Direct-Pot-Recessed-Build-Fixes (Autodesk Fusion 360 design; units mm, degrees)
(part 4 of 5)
work_plane "WorkPlane16" AlongDistance 17 ExtraOffset 0
sketch "Reinforced roof over support-free pivot bore (1)" plane through (17, 0, 0) normal (1, 0, 0) x axis (0, 0, -1)
  line L1 (-17.9, -29) -> (-17.9, -41)
  line L2 (-20, -29) -> (-17.9, -29)
  line L3 (-20, -41) -> (-20, -29)
  line L4 (-17.9, -41) -> (-20, -41)
extrude "Extrude16" add sketch "Reinforced roof over support-free pivot bore (1)" along normal blind 3
work_plane "WorkPlane17" AlongDistance 17 ExtraOffset 0
sketch "Flat print foot below roller cheek (1)" plane through (17, 0, 0) normal (1, 0, 0) x axis (0, 0, -1)
  line L1 (-6, 6) -> (-6, -6)
  line L2 (-12, 6) -> (-6, 6)
  line L3 (-12, -6) -> (-12, 6)
  line L4 (-6, -6) -> (-12, -6)
extrude "Extrude17" add sketch "Flat print foot below roller cheek (1)" along normal blind 3
work_plane "WorkPlane18" AlongDistance 3.9 ExtraOffset 0
sketch "Follower horizontal bore 45 degree roof" plane through (3.9, 0, 0) normal (1, 0, 0) x axis (0, 0, -1)
  line L1 (-14.9345, -32.0655) -> (-14.9345, -37.9345)
  line L2 (-17.869, -35) -> (-14.9345, -32.0655)
  line L3 (-14.9345, -37.9345) -> (-17.869, -35)
extrude "Extrude18" cut sketch "Follower horizontal bore 45 degree roof" along normal blind 16.2
work_plane "WorkPlane19" AlongDistance 3.9 ExtraOffset 0
sketch "Follower horizontal bore 45 degree roof (1)" plane through (3.9, 0, 0) normal (1, 0, 0) x axis (0, 0, -1)
  line L1 (-13.2021, 1.2021) -> (-13.2021, -1.2021)
  line L2 (-14.4042, 0) -> (-13.2021, 1.2021)
  line L3 (-13.2021, -1.2021) -> (-14.4042, 0)
extrude "Extrude19" cut sketch "Follower horizontal bore 45 degree roof (1)" along normal blind 16.2
work_plane "WorkPlane8" AlongDistance 49.65 ExtraOffset 0
sketch "Continuous support beneath lower output prong" plane through (49.65, 0, 0) normal (1, 0, 0) x axis (0, 0, -1)
  line L1 (-57, 2) -> (-57, -2)
  line L2 (-61, 2) -> (-57, 2)
  line L3 (-61, -2) -> (-61, 2)
  line L4 (-57, -2) -> (-61, -2)
extrude "Extrude8" add sketch "Continuous support beneath lower output prong" along normal blind 9
work_plane "WorkPlane11" AlongDistance 9 ExtraOffset 0
sketch "Upright grip head pocket roof" plane through (9, 0, 0) normal (1, 0, 0) x axis (0, 0, -1)
  line L1 (-182.192, -2.192) -> (-182.192, 2.192)
  line L2 (-184.3841, 0) -> (-182.192, -2.192)
  line L3 (-182.192, 2.192) -> (-184.3841, 0)
extrude "Extrude10" cut sketch "Upright grip head pocket roof" along normal blind 16
work_plane "WorkPlane12" AlongDistance 9 ExtraOffset 0
sketch "Upright grip head pocket roof (1)" plane through (9, 0, 0) normal (1, 0, 0) x axis (0, 0, -1)
  line L1 (-192.192, -2.192) -> (-192.192, 2.192)
  line L2 (-194.3841, 0) -> (-192.192, -2.192)
  line L3 (-192.192, 2.192) -> (-194.3841, 0)
extrude "Extrude11" cut sketch "Upright grip head pocket roof (1)" along normal blind 16
work_plane "WorkPlane11" AlongDistance -6.8 ExtraOffset 0
sketch "Shaft half joining insert pocket" plane through (0, -6.8, 0) normal (0, 1, 0) x axis (1, 0, 0)
  circle C1 centre (-15, -65) radius 1.7
extrude "Extrude11" cut sketch "Shaft half joining insert pocket" along normal blind 6.9
work_plane "WorkPlane12" AlongDistance -0.1 ExtraOffset 0
sketch "Shaft half joining screw clearance" plane through (0, -0.1, 0) normal (0, 1, 0) x axis (1, 0, 0)
  circle C1 centre (-15, -65) radius 1.7
extrude "Extrude12" cut sketch "Shaft half joining screw clearance" along normal blind 6.7
work_plane "WorkPlane13" AlongDistance 3.5 ExtraOffset 0
sketch "Flush shaft joining cap head" plane through (0, 3.5, 0) normal (0, 1, 0) x axis (1, 0, 0)
  circle C1 centre (-15, -65) radius 3.1
extrude "Extrude13" cut sketch "Flush shaft joining cap head" along normal blind 3.1
work_plane "WorkPlane1" AlongDistance -4.5 ExtraOffset 0
sketch "Shaft joining M3x8 -15" plane through (0, -4.5, 0) normal (0, 1, 0) x axis (1, 0, 0)
  circle C1 centre (-15, -65) radius 1.5
extrude "Extrude1" new body sketch "Shaft joining M3x8 -15" along normal blind 8 bodies "HARDWARE Shaft joining M3x8 -15"
work_plane "WorkPlane2" AlongDistance 3.5 ExtraOffset 0
sketch "Button head" plane through (0, 3.5, 0) normal (0, 1, 0) x axis (1, 0, 0)
  circle C1 centre (-15, -65) radius 2.75
extrude "Extrude2" add sketch "Button head" along normal blind 3
work_plane "WorkPlane14" AlongDistance -6.8 ExtraOffset 0
sketch "Shaft half joining insert pocket (1)" plane through (0, -6.8, 0) normal (0, 1, 0) x axis (1, 0, 0)
  circle C1 centre (15, -65) radius 1.7
extrude "Extrude14" cut sketch "Shaft half joining insert pocket (1)" along normal blind 6.9
work_plane "WorkPlane15" AlongDistance -0.1 ExtraOffset 0
sketch "Shaft half joining screw clearance (1)" plane through (0, -0.1, 0) normal (0, 1, 0) x axis (1, 0, 0)
  circle C1 centre (15, -65) radius 1.7
extrude "Extrude15" cut sketch "Shaft half joining screw clearance (1)" along normal blind 6.7
work_plane "WorkPlane16" AlongDistance 3.5 ExtraOffset 0
sketch "Flush shaft joining cap head (1)" plane through (0, 3.5, 0) normal (0, 1, 0) x axis (1, 0, 0)
  circle C1 centre (15, -65) radius 3.1
extrude "Extrude16" cut sketch "Flush shaft joining cap head (1)" along normal blind 3.1
work_plane "WorkPlane1" AlongDistance -4.5 ExtraOffset 0
sketch "Shaft joining M3x8 15" plane through (0, -4.5, 0) normal (0, 1, 0) x axis (1, 0, 0)
  circle C1 centre (15, -65) radius 1.5
extrude "Extrude1" new body sketch "Shaft joining M3x8 15" along normal blind 8 bodies "HARDWARE Shaft joining M3x8 15"
work_plane "WorkPlane2" AlongDistance 3.5 ExtraOffset 0
sketch "Button head" plane through (0, 3.5, 0) normal (0, 1, 0) x axis (1, 0, 0)
  circle C1 centre (15, -65) radius 2.75
extrude "Extrude2" add sketch "Button head" along normal blind 3
work_plane "WorkPlane17" AlongDistance -6.6 ExtraOffset 0
sketch "Loose alignment key pocket" plane through (-6.6, 0, 0) normal (1, 0, 0) x axis (0, 0, -1)
  line L1 (-61, 1.6) -> (-61, -1.6)
  line L2 (-69, 1.6) -> (-61, 1.6)
  line L3 (-69, -1.6) -> (-69, 1.6)
  line L4 (-61, -1.6) -> (-69, -1.6)
extrude "Extrude17" cut sketch "Loose alignment key pocket" along normal blind 3.2
work_plane "WorkPlane1" AlongDistance -6.5 ExtraOffset 0
sketch "Loose flat printable alignment key" plane through (-6.5, 0, 0) normal (1, 0, 0) x axis (0, 0, -1)
  line L1 (-61.1, 1.5) -> (-61.1, -1.5)
  line L2 (-68.9, 1.5) -> (-61.1, 1.5)
  line L3 (-68.9, -1.5) -> (-68.9, 1.5)
  line L4 (-61.1, -1.5) -> (-68.9, -1.5)
extrude "Extrude1" new body sketch "Loose flat printable alignment key" along normal blind 3 bodies "P28 Shaft alignment key -5"
work_plane "WorkPlane18" AlongDistance 3.4 ExtraOffset 0
sketch "Loose alignment key pocket (1)" plane through (3.4, 0, 0) normal (1, 0, 0) x axis (0, 0, -1)
  line L1 (-61, 1.6) -> (-61, -1.6)
  line L2 (-69, 1.6) -> (-61, 1.6)
  line L3 (-69, -1.6) -> (-69, 1.6)
  line L4 (-61, -1.6) -> (-69, -1.6)
extrude "Extrude18" cut sketch "Loose alignment key pocket (1)" along normal blind 3.2
work_plane "WorkPlane1" AlongDistance 3.5 ExtraOffset 0
sketch "Loose flat printable alignment key" plane through (3.5, 0, 0) normal (1, 0, 0) x axis (0, 0, -1)
  line L1 (-61.1, 1.5) -> (-61.1, -1.5)
  line L2 (-68.9, 1.5) -> (-61.1, 1.5)
  line L3 (-68.9, -1.5) -> (-68.9, 1.5)
  line L4 (-61.1, -1.5) -> (-68.9, -1.5)
extrude "Extrude1" new body sketch "Loose flat printable alignment key" along normal blind 3 bodies "P28 Shaft alignment key 5"
split "Split1" bodies "P05 Shaft upper half"
work_plane "WorkPlane19" AlongDistance -5 ExtraOffset 0
sketch "Direct cap-head rotor clamp seat" plane through (-5, 0, 0) normal (1, 0, 0) x axis (0, 0, -1)
  line L1 (-60, 22.5) -> (-60, 22)
  line L2 (-70, 22.5) -> (-60, 22.5)
  line L3 (-70, 22) -> (-70, 22.5)
  line L4 (-60, 22) -> (-70, 22)
extrude "Extrude19" add sketch "Direct cap-head rotor clamp seat" along normal blind 10
work_plane "WorkPlane20" AlongDistance 21.9 ExtraOffset 0
sketch "Restore rotor screw through raised seat" plane through (0, 21.9, 0) normal (0, 1, 0) x axis (1, 0, 0)
  circle C1 centre (0, -65) radius 1.7
extrude "Extrude20" cut sketch "Restore rotor screw through raised seat" along normal blind 0.7
work_plane "WorkPlane1" AlongDistance -39.35 ExtraOffset 0
sketch "Main shaft cap M3x8 cap head" plane through (-39.35, 0, 0) normal (1, 0, 0) x axis (0, 0, -1)
  circle C1 centre (-65, 0) radius 1.5
extrude "Extrude1" new body sketch "Main shaft cap M3x8 cap head" along normal blind 8 bodies "HARDWARE Main shaft cap M3x8 cap head"
work_plane "WorkPlane2" AlongDistance -42.35 ExtraOffset 0
sketch "Button head" plane through (-42.35, 0, 0) normal (1, 0, 0) x axis (0, 0, -1)
  circle C1 centre (-65, 0) radius 2.75
extrude "Extrude2" add sketch "Button head" along normal blind 3
work_plane "WorkPlane1" AlongDistance 2 ExtraOffset 0
sketch "Cam M3x10 cap head -45" plane through (2, 0, 0) normal (1, 0, 0) x axis (0, 0, -1)
  circle C1 centre (-39.5442, 25.4558) radius 1.5
extrude "Extrude1" new body sketch "Cam M3x10 cap head -45" along normal blind 10 bodies "HARDWARE Cam M3x10 cap head -45"
work_plane "WorkPlane2" AlongDistance 12 ExtraOffset 0
sketch "Button head" plane through (12, 0, 0) normal (1, 0, 0) x axis (0, 0, -1)
  circle C1 centre (-39.5442, 25.4558) radius 2.75
extrude "Extrude2" add sketch "Button head" along normal blind 3
work_plane "WorkPlane1" AlongDistance 2 ExtraOffset 0
sketch "Cam M3x10 cap head 0" plane through (2, 0, 0) normal (1, 0, 0) x axis (0, 0, -1)
  circle C1 centre (-29, 0) radius 1.5
extrude "Extrude1" new body sketch "Cam M3x10 cap head 0" along normal blind 10 bodies "HARDWARE Cam M3x10 cap head 0"
work_plane "WorkPlane2" AlongDistance 12 ExtraOffset 0
sketch "Button head" plane through (12, 0, 0) normal (1, 0, 0) x axis (0, 0, -1)
  circle C1 centre (-29, 0) radius 2.75
extrude "Extrude2" add sketch "Button head" along normal blind 3
work_plane "WorkPlane1" AlongDistance 2 ExtraOffset 0
sketch "Cam M3x10 cap head 45" plane through (2, 0, 0) normal (1, 0, 0) x axis (0, 0, -1)
  circle C1 centre (-39.5442, -25.4558) radius 1.5
extrude "Extrude1" new body sketch "Cam M3x10 cap head 45" along normal blind 10 bodies "HARDWARE Cam M3x10 cap head 45"
work_plane "WorkPlane2" AlongDistance 12 ExtraOffset 0
sketch "Button head" plane through (12, 0, 0) normal (1, 0, 0) x axis (0, 0, -1)
  circle C1 centre (-39.5442, -25.4558) radius 2.75
extrude "Extrude2" add sketch "Button head" along normal blind 3
work_plane "WorkPlane1" AlongDistance 0 ExtraOffset 0
sketch "Roller axle M3x20 cap head" plane through (0, 0, 0) normal (1, 0, 0) x axis (0, 0, -1)
  circle C1 centre (-12, 0) radius 1.5
extrude "Extrude1" new body sketch "Roller axle M3x20 cap head" along normal blind 20 bodies "HARDWARE Roller axle M3x20 cap head"
work_plane "WorkPlane2" AlongDistance 20 ExtraOffset 0
sketch "Button head" plane through (20, 0, 0) normal (1, 0, 0) x axis (0, 0, -1)
  circle C1 centre (-12, 0) radius 2.75
extrude "Extrude2" add sketch "Button head" along normal blind 3
work_plane "WorkPlane1" AlongDistance -36 ExtraOffset 0
sketch "Crossblock M3x20 cap head (-62, -1)" plane through (-36, 0, 0) normal (1, 0, 0) x axis (0, 0, -1)
  circle C1 centre (-53.5, -62) radius 1.5
extrude "Extrude1" new body sketch "Crossblock M3x20 cap head (-62, -1)" along normal blind 20 bodies "HARDWARE Crossblock M3x20 cap head (-62, -1)"
work_plane "WorkPlane2" AlongDistance -39 ExtraOffset 0
sketch "Button head" plane through (-39, 0, 0) normal (1, 0, 0) x axis (0, 0, -1)
  circle C1 centre (-53.5, -62) radius 2.75
extrude "Extrude2" add sketch "Button head" along normal blind 3
work_plane "WorkPlane1" AlongDistance 16 ExtraOffset 0
sketch "Crossblock M3x20 cap head (-62, 1)" plane through (16, 0, 0) normal (1, 0, 0) x axis (0, 0, -1)
  circle C1 centre (-53.5, -62) radius 1.5
extrude "Extrude1" new body sketch "Crossblock M3x20 cap head (-62, 1)" along normal blind 20 bodies "HARDWARE Crossblock M3x20 cap head (-62, 1)"
work_plane "WorkPlane2" AlongDistance 36 ExtraOffset 0
sketch "Button head" plane through (36, 0, 0) normal (1, 0, 0) x axis (0, 0, -1)
  circle C1 centre (-53.5, -62) radius 2.75
extrude "Extrude2" add sketch "Button head" along normal blind 3
work_plane "WorkPlane1" AlongDistance -36 ExtraOffset 0
sketch "Crossblock M3x20 cap head (-70, -1)" plane through (-36, 0, 0) normal (1, 0, 0) x axis (0, 0, -1)
  circle C1 centre (-53.5, -70) radius 1.5
extrude "Extrude1" new body sketch "Crossblock M3x20 cap head (-70, -1)" along normal blind 20 bodies "HARDWARE Crossblock M3x20 cap head (-70, -1)"
work_plane "WorkPlane2" AlongDistance -39 ExtraOffset 0
sketch "Button head" plane through (-39, 0, 0) normal (1, 0, 0) x axis (0, 0, -1)
  circle C1 centre (-53.5, -70) radius 2.75
extrude "Extrude2" add sketch "Button head" along normal blind 3
work_plane "WorkPlane1" AlongDistance 16 ExtraOffset 0
sketch "Crossblock M3x20 cap head (-70, 1)" plane through (16, 0, 0) normal (1, 0, 0) x axis (0, 0, -1)
  circle C1 centre (-53.5, -70) radius 1.5
extrude "Extrude1" new body sketch "Crossblock M3x20 cap head (-70, 1)" along normal blind 20 bodies "HARDWARE Crossblock M3x20 cap head (-70, 1)"
work_plane "WorkPlane2" AlongDistance 36 ExtraOffset 0
sketch "Button head" plane through (36, 0, 0) normal (1, 0, 0) x axis (0, 0, -1)
  circle C1 centre (-53.5, -70) radius 2.75
extrude "Extrude2" add sketch "Button head" along normal blind 3
work_plane "WorkPlane1" AlongDistance 6.5 ExtraOffset 0
sketch "Rotor clamp M3x16 cap head" plane through (0, 6.5, 0) normal (0, 1, 0) x axis (1, 0, 0)
  circle C1 centre (0, -65) radius 1.5
extrude "Extrude1" new body sketch "Rotor clamp M3x16 cap head" along normal blind 16 bodies "HARDWARE Rotor clamp M3x16 cap head"
work_plane "WorkPlane2" AlongDistance 22.5 ExtraOffset 0
sketch "Button head" plane through (0, 22.5, 0) normal (0, 1, 0) x axis (1, 0, 0)
  circle C1 centre (0, -65) radius 2.75
extrude "Extrude2" add sketch "Button head" along normal blind 3
work_plane "WorkPlane20" AlongDistance 3.9 ExtraOffset 0
sketch "Restore axle bore after adding print feet" plane through (3.9, 0, 0) normal (1, 0, 0) x axis (0, 0, -1)
  circle C1 centre (-12, 0) radius 1.7
extrude "Extrude20" cut sketch "Restore axle bore after adding print feet" along normal blind 16.2
work_plane "WorkPlane21" AlongDistance 3.9 ExtraOffset 0
sketch "Restore nut installation recess after print foot" plane through (3.9, 0, 0) normal (1, 0, 0) x axis (0, 0, -1)
  line L1 (-14.9, 1.6743) -> (-12, 3.3486)
  line L2 (-14.9, -1.6743) -> (-14.9, 1.6743)
  line L3 (-12, -3.3486) -> (-14.9, -1.6743)
  line L4 (-9.1, -1.6743) -> (-12, -3.3486)
  line L5 (-9.1, 1.6743) -> (-9.1, -1.6743)
  line L6 (-12, 3.3486) -> (-9.1, 1.6743)
extrude "Extrude21" cut sketch "Restore nut installation recess after print foot" along normal blind 1.6
work_plane "WorkPlane3" AlongDistance 8 ExtraOffset 0
sketch "Retain one mm preload travel before head meets collar" plane through (8, 0, 0) normal (1, 0, 0) x axis (0, 0, -1)
  line L1 (-56, -51) -> (-56, -59)
  line L2 (-57.1, -51) -> (-56, -51)
  line L3 (-57.1, -59) -> (-57.1, -51)
  line L4 (-56, -59) -> (-57.1, -59)
extrude "Extrude3" cut sketch "Retain one mm preload travel before head meets collar" along normal blind 8
work_plane "WorkPlane63" AlongDistance 20.8 ExtraOffset 0
sketch "Clear stocked carriage screw tip beyond insert" plane through (0, 20.8, 0) normal (0, 1, 0) x axis (1, 0, 0)
  circle C1 centre (60.15, -65) radius 1.7
extrude "Extrude63" cut sketch "Clear stocked carriage screw tip beyond insert" along normal blind 0.6
work_plane "WorkPlane64" AlongDistance -21.4 ExtraOffset 0
sketch "Clear stocked carriage screw tip beyond insert (1)" plane through (0, -21.4, 0) normal (0, 1, 0) x axis (1, 0, 0)
  circle C1 centre (60.15, -65) radius 1.7
extrude "Extrude64" cut sketch "Clear stocked carriage screw tip beyond insert (1)" along normal blind 0.6
work_plane "WorkPlane22" AlongDistance -2.5 ExtraOffset 0
sketch "Support-free lower ramp under left inner-race pad" plane through (0, -2.5, 0) normal (0, 1, 0) x axis (1, 0, 0)
  line L1 (8.1, -9.5) -> (7, -9.5)
  line L2 (8.1, -10.7) -> (8.1, -9.5)
  line L3 (7, -9.6) -> (8.1, -10.7)
  line L4 (7, -9.5) -> (7, -9.6)
extrude "Extrude22" cut sketch "Support-free lower ramp under left inner-race pad" along normal blind 5
work_plane "WorkPlane23" AlongDistance -2.5 ExtraOffset 0
sketch "Support-free lower ramp under right inner-race pad" plane through (0, -2.5, 0) normal (0, 1, 0) x axis (1, 0, 0)
  line L1 (17, -9.5) -> (15.9, -9.5)
  line L2 (17, -9.6) -> (17, -9.5)
  line L3 (15.9, -10.7) -> (17, -9.6)
  line L4 (15.9, -9.5) -> (15.9, -10.7)
extrude "Extrude23" cut sketch "Support-free lower ramp under right inner-race pad" along normal blind 5
ground "Pin94"
ground "Pin95"
ground "Pin96"
ground "Pin97"
ground "Pin98"
ground "Pin99"
ground "Pin100"
ground "Pin101"
ground "Pin102"
ground "Pin103"
ground "Pin104"
ground "Pin105"
ground "Pin106"
ground "Pin107"
ground "Pin108"
ground "Pin109"
ground "Pin110"
ground "Pin111"
ground "Pin112"
ground "Pin113"
ground "Pin114"
ground "Pin115"
ground "Pin116"
ground "Pin120"
ground "Pin121"
ground "Pin122"
ground "Pin123"
ground "Unpin124"
ground "Unpin125"
ground "Unpin126"
ground "Unpin127"
ground "Unpin128"
ground "Unpin129"
ground "Unpin130"
ground "Unpin131"
ground "Unpin132"
ground "Unpin133"
ground "Unpin134"
ground "Unpin135"
ground "Unpin136"
ground "Unpin137"
ground "Unpin138"
ground "Unpin139"
ground "Unpin140"
ground "Unpin141"
ground "Unpin142"
ground "Unpin143"
ground "Unpin144"
ground "Unpin145"
ground "Unpin146"
ground "Unpin147"
ground "Unpin148"
ground "Unpin149"
ground "Unpin150"
ground "Unpin151"
ground "Unpin152"
ground "Unpin153"
ground "Unpin154"
ground "Unpin155"
ground "Unpin156"
ground "Unpin160"
ground "Unpin161"
ground "Unpin162"
ground "Unpin163"
split "Split1" bodies "P04 Right bush upper half"
work_plane "WorkPlane68" AlongDistance -36.1 ExtraOffset 0
sketch "Remove former rail tab before recess" plane through (-36.1, 0, 0) normal (1, 0, 0) x axis (0, 0, -1)
  line L1 (-54.9, -74.5) -> (-54.9, -96)
  line L2 (-64.2, -74.5) -> (-54.9, -74.5)
  line L3 (-64.2, -96) -> (-64.2, -74.5)
  line L4 (-54.9, -96) -> (-64.2, -96)
extrude "Extrude68" cut sketch "Remove former rail tab before recess" along normal blind 12.2
work_plane "WorkPlane69" AlongDistance -36 ExtraOffset 0
sketch "Continuous recessed hanging tower" plane through (-36, 0, 0) normal (1, 0, 0) x axis (0, 0, -1)
  line L1 (-55, -63) -> (-55, -74.5)
  line L2 (-99, -63) -> (-55, -63)
  line L3 (-99, -74.5) -> (-99, -63)
  line L4 (-55, -74.5) -> (-99, -74.5)
extrude "Extrude69" add sketch "Continuous recessed hanging tower" along normal blind 12
work_plane "WorkPlane70" AlongDistance -36 ExtraOffset 0
sketch "Top rail seat unchanged after 35 mm drop" plane through (-36, 0, 0) normal (1, 0, 0) x axis (0, 0, -1)
  line L1 (-90, -63) -> (-90, -95)
  line L2 (-99, -63) -> (-90, -63)
  line L3 (-99, -95) -> (-99, -63)
  line L4 (-90, -95) -> (-99, -95)
extrude "Extrude70" add sketch "Top rail seat unchanged after 35 mm drop" along normal blind 12
work_plane "WorkPlane71" AlongDistance 89.9 ExtraOffset 0
sketch "Rail clearance at retained world seat" plane through (0, 0, 89.9) normal (0, 0, 1) x axis (1, 0, 0)
  circle C1 centre (-30, -85) radius 2.7
extrude "Extrude71" cut sketch "Rail clearance at retained world seat" along normal blind 9.2
work_plane "WorkPlane72" AlongDistance 89.9 ExtraOffset 0
sketch "Rail bore 45 degree print roof" plane through (0, 0, 89.9) normal (0, 0, 1) x axis (1, 0, 0)
  line L1 (-28.0908, -83.0908) -> (-28.0908, -86.9092)
  line L2 (-26.1816, -85) -> (-28.0908, -83.0908)
  line L3 (-28.0908, -86.9092) -> (-26.1816, -85)
extrude "Extrude72" cut sketch "Rail bore 45 degree print roof" along normal blind 9.2
work_plane "WorkPlane73" AlongDistance -36.1 ExtraOffset 0
sketch "Remove former rail tab before recess (1)" plane through (-36.1, 0, 0) normal (1, 0, 0) x axis (0, 0, -1)
  line L1 (-54.9, 96) -> (-54.9, 74.5)
  line L2 (-64.2, 96) -> (-54.9, 96)
  line L3 (-64.2, 74.5) -> (-64.2, 96)
  line L4 (-54.9, 74.5) -> (-64.2, 74.5)
extrude "Extrude73" cut sketch "Remove former rail tab before recess (1)" along normal blind 12.2
work_plane "WorkPlane74" AlongDistance -36 ExtraOffset 0
sketch "Continuous recessed hanging tower (1)" plane through (-36, 0, 0) normal (1, 0, 0) x axis (0, 0, -1)
  line L1 (-55, 74.5) -> (-55, 63)
  line L2 (-99, 74.5) -> (-55, 74.5)
  line L3 (-99, 63) -> (-99, 74.5)
  line L4 (-55, 63) -> (-99, 63)
extrude "Extrude74" add sketch "Continuous recessed hanging tower (1)" along normal blind 12
work_plane "WorkPlane75" AlongDistance -36 ExtraOffset 0
sketch "Top rail seat unchanged after 35 mm drop (1)" plane through (-36, 0, 0) normal (1, 0, 0) x axis (0, 0, -1)
  line L1 (-90, 95) -> (-90, 63)
  line L2 (-99, 95) -> (-90, 95)
  line L3 (-99, 63) -> (-99, 95)
  line L4 (-90, 63) -> (-99, 63)
extrude "Extrude75" add sketch "Top rail seat unchanged after 35 mm drop (1)" along normal blind 12
work_plane "WorkPlane76" AlongDistance 89.9 ExtraOffset 0
sketch "Rail clearance at retained world seat (1)" plane through (0, 0, 89.9) normal (0, 0, 1) x axis (1, 0, 0)
  circle C1 centre (-30, 85) radius 2.7
extrude "Extrude76" cut sketch "Rail clearance at retained world seat (1)" along normal blind 9.2
work_plane "WorkPlane77" AlongDistance 89.9 ExtraOffset 0
sketch "Rail bore 45 degree print roof (1)" plane through (0, 0, 89.9) normal (0, 0, 1) x axis (1, 0, 0)
  line L1 (-28.0908, 86.9092) -> (-28.0908, 83.0908)
  line L2 (-26.1816, 85) -> (-28.0908, 86.9092)
  line L3 (-28.0908, 83.0908) -> (-26.1816, 85)
extrude "Extrude77" cut sketch "Rail bore 45 degree print roof (1)" along normal blind 9.2
work_plane "WorkPlane65" AlongDistance 23.9 ExtraOffset 0
sketch "Remove former rail tab before recess" plane through (23.9, 0, 0) normal (1, 0, 0) x axis (0, 0, -1)
  line L1 (-54.9, -74.5) -> (-54.9, -96)
  line L2 (-64.2, -74.5) -> (-54.9, -74.5)
  line L3 (-64.2, -96) -> (-64.2, -74.5)
  line L4 (-54.9, -96) -> (-64.2, -96)
extrude "Extrude65" cut sketch "Remove former rail tab before recess" along normal blind 12.2
work_plane "WorkPlane66" AlongDistance 24 ExtraOffset 0
sketch "Continuous recessed hanging tower" plane through (24, 0, 0) normal (1, 0, 0) x axis (0, 0, -1)
  line L1 (-55, -63) -> (-55, -74.5)
  line L2 (-99, -63) -> (-55, -63)
  line L3 (-99, -74.5) -> (-99, -63)
  line L4 (-55, -74.5) -> (-99, -74.5)
extrude "Extrude66" add sketch "Continuous recessed hanging tower" along normal blind 12
work_plane "WorkPlane67" AlongDistance 24 ExtraOffset 0
sketch "Top rail seat unchanged after 35 mm drop" plane through (24, 0, 0) normal (1, 0, 0) x axis (0, 0, -1)
  line L1 (-90, -63) -> (-90, -95)
  line L2 (-99, -63) -> (-90, -63)
  line L3 (-99, -95) -> (-99, -63)
  line L4 (-90, -95) -> (-99, -95)
extrude "Extrude67" add sketch "Top rail seat unchanged after 35 mm drop" along normal blind 12
work_plane "WorkPlane68" AlongDistance 89.9 ExtraOffset 0
sketch "Rail clearance at retained world seat" plane through (0, 0, 89.9) normal (0, 0, 1) x axis (1, 0, 0)
  circle C1 centre (30, -85) radius 2.7
extrude "Extrude68" cut sketch "Rail clearance at retained world seat" along normal blind 9.2
work_plane "WorkPlane69" AlongDistance 89.9 ExtraOffset 0
sketch "Rail bore 45 degree print roof" plane through (0, 0, 89.9) normal (0, 0, 1) x axis (1, 0, 0)
  line L1 (31.9092, -83.0908) -> (31.9092, -86.9092)
  line L2 (33.8184, -85) -> (31.9092, -83.0908)
  line L3 (31.9092, -86.9092) -> (33.8184, -85)
extrude "Extrude69" cut sketch "Rail bore 45 degree print roof" along normal blind 9.2
work_plane "WorkPlane70" AlongDistance 23.9 ExtraOffset 0
sketch "Remove former rail tab before recess (1)" plane through (23.9, 0, 0) normal (1, 0, 0) x axis (0, 0, -1)
  line L1 (-54.9, 96) -> (-54.9, 74.5)
  line L2 (-64.2, 96) -> (-54.9, 96)
  line L3 (-64.2, 74.5) -> (-64.2, 96)
  line L4 (-54.9, 74.5) -> (-64.2, 74.5)
extrude "Extrude70" cut sketch "Remove former rail tab before recess (1)" along normal blind 12.2
work_plane "WorkPlane71" AlongDistance 24 ExtraOffset 0
sketch "Continuous recessed hanging tower (1)" plane through (24, 0, 0) normal (1, 0, 0) x axis (0, 0, -1)
  line L1 (-55, 74.5) -> (-55, 63)
  line L2 (-99, 74.5) -> (-55, 74.5)
  line L3 (-99, 63) -> (-99, 74.5)
  line L4 (-55, 63) -> (-99, 63)
extrude "Extrude71" add sketch "Continuous recessed hanging tower (1)" along normal blind 12
work_plane "WorkPlane72" AlongDistance 24 ExtraOffset 0
sketch "Top rail seat unchanged after 35 mm drop (1)" plane through (24, 0, 0) normal (1, 0, 0) x axis (0, 0, -1)
  line L1 (-90, 95) -> (-90, 63)
  line L2 (-99, 95) -> (-90, 95)
  line L3 (-99, 63) -> (-99, 95)
  line L4 (-90, 63) -> (-99, 63)
extrude "Extrude72" add sketch "Top rail seat unchanged after 35 mm drop (1)" along normal blind 12
work_plane "WorkPlane73" AlongDistance 89.9 ExtraOffset 0
sketch "Rail clearance at retained world seat (1)" plane through (0, 0, 89.9) normal (0, 0, 1) x axis (1, 0, 0)
  circle C1 centre (30, 85) radius 2.7
extrude "Extrude73" cut sketch "Rail clearance at retained world seat (1)" along normal blind 9.2
work_plane "WorkPlane74" AlongDistance 89.9 ExtraOffset 0
sketch "Rail bore 45 degree print roof (1)" plane through (0, 0, 89.9) normal (0, 0, 1) x axis (1, 0, 0)
  line L1 (31.9092, 86.9092) -> (31.9092, 83.0908)
  line L2 (33.8184, 85) -> (31.9092, 86.9092)
  line L3 (31.9092, 83.0908) -> (33.8184, 85)
extrude "Extrude74" cut sketch "Rail bore 45 degree print roof (1)" along normal blind 9.2
work_plane "WorkPlane78" AlongDistance -31.5 ExtraOffset 0
sketch "Counterbore first anchored bridge relief" plane through (-31.5, 0, 0) normal (1, 0, 0) x axis (0, 0, -1)
  line L1 (-77.9754, -30.8652) -> (-77.9754, -37.0652)
  line L2 (-81.3754, -30.8652) -> (-77.9754, -30.8652)
  line L3 (-81.3754, -37.0652) -> (-81.3754, -30.8652)
  line L4 (-77.9754, -37.0652) -> (-81.3754, -37.0652)
extrude "Extrude78" cut sketch "Counterbore first anchored bridge relief" along normal blind 0.2
work_plane "WorkPlane79" AlongDistance -31.3 ExtraOffset 0
sketch "Counterbore crossed bridge relief" plane through (-31.3, 0, 0) normal (1, 0, 0) x axis (0, 0, -1)
  line L1 (-77.9754, -32.2652) -> (-77.9754, -35.6652)
  line L2 (-81.3754, -32.2652) -> (-77.9754, -32.2652)
  line L3 (-81.3754, -35.6652) -> (-81.3754, -32.2652)
  line L4 (-77.9754, -35.6652) -> (-81.3754, -35.6652)
extrude "Extrude79" cut sketch "Counterbore crossed bridge relief" along normal blind 0.2
work_plane "WorkPlane80" AlongDistance -31.5 ExtraOffset 0
sketch "Counterbore first anchored bridge relief (1)" plane through (-31.5, 0, 0) normal (1, 0, 0) x axis (0, 0, -1)
  line L1 (-77.9754, 37.0652) -> (-77.9754, 30.8652)
  line L2 (-81.3754, 37.0652) -> (-77.9754, 37.0652)
  line L3 (-81.3754, 30.8652) -> (-81.3754, 37.0652)
  line L4 (-77.9754, 30.8652) -> (-81.3754, 30.8652)
extrude "Extrude80" cut sketch "Counterbore first anchored bridge relief (1)" along normal blind 0.2
work_plane "WorkPlane81" AlongDistance -31.3 ExtraOffset 0
sketch "Counterbore crossed bridge relief (1)" plane through (-31.3, 0, 0) normal (1, 0, 0) x axis (0, 0, -1)
  line L1 (-77.9754, 35.6652) -> (-77.9754, 32.2652)
  line L2 (-81.3754, 35.6652) -> (-77.9754, 35.6652)
  line L3 (-81.3754, 32.2652) -> (-81.3754, 35.6652)
  line L4 (-77.9754, 32.2652) -> (-81.3754, 32.2652)
extrude "Extrude81" cut sketch "Counterbore crossed bridge relief (1)" along normal blind 0.2
work_plane "WorkPlane75" AlongDistance -28.1 ExtraOffset 0
sketch "Close old insert pocket" plane through (0, -28.1, 0) normal (0, 1, 0) x axis (1, 0, 0)
  circle C1 centre (60.15, -65) radius 2.01
extrude "Extrude75" add sketch "Close old insert pocket" along normal blind 6.8
work_plane "WorkPlane76" AlongDistance 62.95 ExtraOffset 0
sketch "Measured pot panel inward clearance" plane through (62.95, 0, 0) normal (1, 0, 0) x axis (0, 0, -1)
  line L1 (-55.9, -18) -> (-55.9, -28)
  line L2 (-81.1, -18) -> (-55.9, -18)
  line L3 (-81.1, -28) -> (-81.1, -18)
  line L4 (-55.9, -28) -> (-81.1, -28)
extrude "Extrude76" cut sketch "Measured pot panel inward clearance" along normal blind 3.35
work_plane "WorkPlane77" AlongDistance -25 ExtraOffset 0
sketch "Side-loaded carriage nut" plane through (0, -25, 0) normal (0, 1, 0) x axis (1, 0, 0)
  line L1 (59.8243, -67.9) -> (61.4986, -65)
  line L2 (56.4757, -67.9) -> (59.8243, -67.9)
  line L3 (54.8014, -65) -> (56.4757, -67.9)
  line L4 (56.4757, -62.1) -> (54.8014, -65)
  line L5 (59.8243, -62.1) -> (56.4757, -62.1)
  line L6 (61.4986, -65) -> (59.8243, -62.1)
extrude "Extrude77" cut sketch "Side-loaded carriage nut" along normal blind 2.6
work_plane "WorkPlane78" AlongDistance 58.15 ExtraOffset 0
sketch "Nut insertion from panel end" plane through (58.15, 0, 0) normal (1, 0, 0) x axis (0, 0, -1)
  line L1 (-62.1, -22.4) -> (-62.1, -25)
  line L2 (-67.9, -22.4) -> (-62.1, -22.4)
  line L3 (-67.9, -25) -> (-67.9, -22.4)
  line L4 (-62.1, -25) -> (-67.9, -25)
extrude "Extrude78" cut sketch "Nut insertion from panel end" along normal blind 4.9
work_plane "WorkPlane79" AlongDistance -28.1 ExtraOffset 0
sketch "Carriage screw to captive nut" plane through (0, -28.1, 0) normal (0, 1, 0) x axis (1, 0, 0)
  circle C1 centre (58.15, -65) radius 1.7
extrude "Extrude79" cut sketch "Carriage screw to captive nut" along normal blind 7.3
work_plane "WorkPlane80" AlongDistance 21.3 ExtraOffset 0
sketch "Close old insert pocket (1)" plane through (0, 21.3, 0) normal (0, 1, 0) x axis (1, 0, 0)
  circle C1 centre (60.15, -65) radius 2.01
extrude "Extrude80" add sketch "Close old insert pocket (1)" along normal blind 6.8
work_plane "WorkPlane81" AlongDistance 62.95 ExtraOffset 0
sketch "Measured pot panel inward clearance (1)" plane through (62.95, 0, 0) normal (1, 0, 0) x axis (0, 0, -1)
  line L1 (-55.9, 28) -> (-55.9, 18)
  line L2 (-81.1, 28) -> (-55.9, 28)
  line L3 (-81.1, 18) -> (-81.1, 28)
  line L4 (-55.9, 18) -> (-81.1, 18)
extrude "Extrude81" cut sketch "Measured pot panel inward clearance (1)" along normal blind 3.35
work_plane "WorkPlane82" AlongDistance 22.4 ExtraOffset 0
sketch "Side-loaded carriage nut (1)" plane through (0, 22.4, 0) normal (0, 1, 0) x axis (1, 0, 0)
  line L1 (59.8243, -67.9) -> (61.4986, -65)
  line L2 (56.4757, -67.9) -> (59.8243, -67.9)
  line L3 (54.8014, -65) -> (56.4757, -67.9)
  line L4 (56.4757, -62.1) -> (54.8014, -65)
  line L5 (59.8243, -62.1) -> (56.4757, -62.1)
  line L6 (61.4986, -65) -> (59.8243, -62.1)
extrude "Extrude82" cut sketch "Side-loaded carriage nut (1)" along normal blind 2.6
work_plane "WorkPlane83" AlongDistance 58.15 ExtraOffset 0
sketch "Nut insertion from panel end (1)" plane through (58.15, 0, 0) normal (1, 0, 0) x axis (0, 0, -1)
  line L1 (-62.1, 25) -> (-62.1, 22.4)
  line L2 (-67.9, 25) -> (-62.1, 25)
  line L3 (-67.9, 22.4) -> (-67.9, 25)
  line L4 (-62.1, 22.4) -> (-67.9, 22.4)
extrude "Extrude83" cut sketch "Nut insertion from panel end (1)" along normal blind 4.9
work_plane "WorkPlane84" AlongDistance 20.8 ExtraOffset 0
sketch "Carriage screw to captive nut (1)" plane through (0, 20.8, 0) normal (0, 1, 0) x axis (1, 0, 0)
  circle C1 centre (58.15, -65) radius 1.7
extrude "Extrude84" cut sketch "Carriage screw to captive nut (1)" along normal blind 7.3
work_plane "WorkPlane1" AlongDistance 65.95 ExtraOffset 0
sketch "Measured body 11.2 x 9.5 x 6.6" plane through (65.95, 0, 0) normal (1, 0, 0) x axis (0, 0, -1)
  line L1 (-60.25, 5.6) -> (-60.25, -5.6)
  line L2 (-69.75, 5.6) -> (-60.25, 5.6)
  line L3 (-69.75, -5.6) -> (-69.75, 5.6)
  line L4 (-60.25, -5.6) -> (-69.75, -5.6)
extrude "Extrude1" new body sketch "Measured body 11.2 x 9.5 x 6.6" along normal blind 6.6
work_plane "WorkPlane2" AlongDistance 58.95 ExtraOffset 0
sketch "Inferred 7 mm M7 bushing" plane through (58.95, 0, 0) normal (1, 0, 0) x axis (0, 0, -1)
  circle C1 centre (-65, 0) radius 3.5
extrude "Extrude2" add sketch "Inferred 7 mm M7 bushing" along normal blind 7
work_plane "WorkPlane3" AlongDistance 50.95 ExtraOffset 0
sketch "Measured 8 mm rotating shaft" plane through (50.95, 0, 0) normal (1, 0, 0) x axis (0, 0, -1)
  circle C1 centre (-65, 0) radius 3
extrude "Extrude3" add sketch "Measured 8 mm rotating shaft" along normal blind 8
work_plane "WorkPlane1" AlongDistance 62.45 ExtraOffset 0
sketch "Pot supplied washer assumed" plane through (62.45, 0, 0) normal (1, 0, 0) x axis (0, 0, -1)
  circle C1 centre (-65, 0) radius 6
extrude "Extrude1" new body sketch "Pot supplied washer assumed" along normal blind 0.5 bodies "HARDWARE Pot supplied washer assumed"
work_plane "WorkPlane2" AlongDistance 62.35 ExtraOffset 0
sketch "Washer clearance" plane through (62.35, 0, 0) normal (1, 0, 0) x axis (0, 0, -1)
  circle C1 centre (-65, 0) radius 3.6
extrude "Extrude2" cut sketch "Washer clearance" along normal blind 0.7
work_plane "WorkPlane1" AlongDistance 60.45 ExtraOffset 0
sketch "Pot supplied M7 nut assumed" plane through (60.45, 0, 0) normal (1, 0, 0) x axis (0, 0, -1)
  line L1 (-70.5, 3.1754) -> (-65, 6.3509)
  line L2 (-70.5, -3.1754) -> (-70.5, 3.1754)
  line L3 (-65, -6.3509) -> (-70.5, -3.1754)
  line L4 (-59.5, -3.1754) -> (-65, -6.3509)
  line L5 (-59.5, 3.1754) -> (-59.5, -3.1754)
  line L6 (-65, 6.3509) -> (-59.5, 3.1754)
extrude "Extrude1" new body sketch "Pot supplied M7 nut assumed" along normal blind 2 bodies "HARDWARE Pot supplied M7 nut assumed"
work_plane "WorkPlane2" AlongDistance 60.35 ExtraOffset 0
sketch "Thread envelope" plane through (60.35, 0, 0) normal (1, 0, 0) x axis (0, 0, -1)
  circle C1 centre (-65, 0) radius 3.5
extrude "Extrude2" cut sketch "Thread envelope" along normal blind 2.2
work_plane "WorkPlane1" AlongDistance -24.9 ExtraOffset 0
sketch "Carriage captured M3 -1" plane through (0, -24.9, 0) normal (0, 1, 0) x axis (1, 0, 0)
  line L1 (59.7377, -67.75) -> (61.3254, -65)
  line L2 (56.5623, -67.75) -> (59.7377, -67.75)
  line L3 (54.9746, -65) -> (56.5623, -67.75)
  line L4 (56.5623, -62.25) -> (54.9746, -65)
  line L5 (59.7377, -62.25) -> (56.5623, -62.25)
  line L6 (61.3254, -65) -> (59.7377, -62.25)
extrude "Extrude1" new body sketch "Carriage captured M3 -1" along normal blind 2.4 bodies "HARDWARE Carriage captured M3 -1"
work_plane "WorkPlane2" AlongDistance -25 ExtraOffset 0
sketch "Thread envelope" plane through (0, -25, 0) normal (0, 1, 0) x axis (1, 0, 0)
  circle C1 centre (58.15, -65) radius 1.5
extrude "Extrude2" cut sketch "Thread envelope" along normal blind 2.6
work_plane "WorkPlane1" AlongDistance 22.5 ExtraOffset 0
sketch "Carriage captured M3 1" plane through (0, 22.5, 0) normal (0, 1, 0) x axis (1, 0, 0)
  line L1 (59.7377, -67.75) -> (61.3254, -65)
  line L2 (56.5623, -67.75) -> (59.7377, -67.75)
  line L3 (54.9746, -65) -> (56.5623, -67.75)
  line L4 (56.5623, -62.25) -> (54.9746, -65)
  line L5 (59.7377, -62.25) -> (56.5623, -62.25)
  line L6 (61.3254, -65) -> (59.7377, -62.25)
extrude "Extrude1" new body sketch "Carriage captured M3 1" along normal blind 2.4 bodies "HARDWARE Carriage captured M3 1"
work_plane "WorkPlane2" AlongDistance 22.4 ExtraOffset 0
sketch "Thread envelope" plane through (0, 22.4, 0) normal (0, 1, 0) x axis (1, 0, 0)
  circle C1 centre (58.15, -65) radius 1.5
extrude "Extrude2" cut sketch "Thread envelope" along normal blind 2.6
work_plane "WorkPlane54" AlongDistance 38 ExtraOffset 0
sketch "Close insert pilot for captive nut conversion" plane through (0, 0, 38) normal (0, 0, 1) x axis (1, 0, 0)
  circle C1 centre (4, -55) radius 2.01
extrude "Extrude54" add sketch "Close insert pilot for captive nut conversion" along normal blind 6.8
work_plane "WorkPlane55" AlongDistance 37.9 ExtraOffset 0
sketch "M3 clearance through nut interface" plane through (0, 0, 37.9) normal (0, 0, 1) x axis (1, 0, 0)
  circle C1 centre (4, -55) radius 1.7
extrude "Extrude55" cut sketch "M3 clearance through nut interface" along normal blind 7
work_plane "WorkPlane56" AlongDistance 38 ExtraOffset 0
sketch "Close insert pilot for captive nut conversion (1)" plane through (0, 0, 38) normal (0, 0, 1) x axis (1, 0, 0)
  circle C1 centre (12, -55) radius 2.01
extrude "Extrude56" add sketch "Close insert pilot for captive nut conversion (1)" along normal blind 6.8
work_plane "WorkPlane57" AlongDistance 37.9 ExtraOffset 0
sketch "M3 clearance through nut interface (1)" plane through (0, 0, 37.9) normal (0, 0, 1) x axis (1, 0, 0)
  circle C1 centre (12, -55) radius 1.7
extrude "Extrude57" cut sketch "M3 clearance through nut interface (1)" along normal blind 21.2
work_plane "WorkPlane58" AlongDistance 38 ExtraOffset 0
sketch "Close insert pilot for captive nut conversion (2)" plane through (0, 0, 38) normal (0, 0, 1) x axis (1, 0, 0)
  circle C1 centre (20, -55) radius 2.01
extrude "Extrude58" add sketch "Close insert pilot for captive nut conversion (2)" along normal blind 6.8
work_plane "WorkPlane59" AlongDistance 37.9 ExtraOffset 0
sketch "M3 clearance through nut interface (2)" plane through (0, 0, 37.9) normal (0, 0, 1) x axis (1, 0, 0)
  circle C1 centre (20, -55) radius 1.7
extrude "Extrude59" cut sketch "M3 clearance through nut interface (2)" along normal blind 7
work_plane "WorkPlane60" AlongDistance 37.9 ExtraOffset 0
sketch "Bottom loaded preload reaction nut" plane through (0, 0, 37.9) normal (0, 0, 1) x axis (1, 0, 0)
  line L1 (13.6743, -52.1) -> (15.3486, -55)
  line L2 (10.3257, -52.1) -> (13.6743, -52.1)
  line L3 (8.6514, -55) -> (10.3257, -52.1)
  line L4 (10.3257, -57.9) -> (8.6514, -55)
  line L5 (13.6743, -57.9) -> (10.3257, -57.9)
  line L6 (15.3486, -55) -> (13.6743, -57.9)
extrude "Extrude60" cut sketch "Bottom loaded preload reaction nut" along normal blind 2.7
work_plane "WorkPlane1" AlongDistance 38.1 ExtraOffset 0
sketch "Preload bottom reaction M3 nut" plane through (0, 0, 38.1) normal (0, 0, 1) x axis (1, 0, 0)
  line L1 (13.5877, -52.25) -> (15.1754, -55)
  line L2 (10.4123, -52.25) -> (13.5877, -52.25)
  line L3 (8.8246, -55) -> (10.4123, -52.25)
  line L4 (10.4123, -57.75) -> (8.8246, -55)
  line L5 (13.5877, -57.75) -> (10.4123, -57.75)
  line L6 (15.1754, -55) -> (13.5877, -57.75)
extrude "Extrude1" new body sketch "Preload bottom reaction M3 nut" along normal blind 2.4 bodies "HARDWARE Preload bottom reaction M3 nut"
work_plane "WorkPlane2" AlongDistance 38 ExtraOffset 0
sketch "Thread envelope" plane through (0, 0, 38) normal (0, 0, 1) x axis (1, 0, 0)
  circle C1 centre (12, -55) radius 1.5
extrude "Extrude2" cut sketch "Thread envelope" along normal blind 2.6
work_plane "WorkPlane61" AlongDistance 40.8 ExtraOffset 0
sketch "Guide captive nut with lower reaction shoulder" plane through (0, 0, 40.8) normal (0, 0, 1) x axis (1, 0, 0)
  line L1 (4, -51.6514) -> (6.9, -53.3257)
  line L2 (1.1, -53.3257) -> (4, -51.6514)
  line L3 (1.1, -56.6743) -> (1.1, -53.3257)
  line L4 (4, -58.3486) -> (1.1, -56.6743)
  line L5 (6.9, -56.6743) -> (4, -58.3486)
  line L6 (6.9, -53.3257) -> (6.9, -56.6743)
extrude "Extrude61" cut sketch "Guide captive nut with lower reaction shoulder" along normal blind 2.6
work_plane "WorkPlane62" AlongDistance 1.1 ExtraOffset 0
sketch "Guide nut rear installation slot" plane through (1.1, 0, 0) normal (1, 0, 0) x axis (0, 0, -1)
  line L1 (-40.8, -55) -> (-40.8, -74.1)
  line L2 (-43.4, -55) -> (-40.8, -55)
  line L3 (-43.4, -74.1) -> (-43.4, -55)
  line L4 (-40.8, -74.1) -> (-43.4, -74.1)
extrude "Extrude62" cut sketch "Guide nut rear installation slot" along normal blind 5.8
work_plane "WorkPlane63" AlongDistance 1.1 ExtraOffset 0
sketch "Guide nut first bridge relief" plane through (1.1, 0, 0) normal (1, 0, 0) x axis (0, 0, -1)
  line L1 (-40.6, -53.3) -> (-40.6, -56.7)
  line L2 (-40.8, -53.3) -> (-40.6, -53.3)
  line L3 (-40.8, -56.7) -> (-40.8, -53.3)
  line L4 (-40.6, -56.7) -> (-40.8, -56.7)
extrude "Extrude63" cut sketch "Guide nut first bridge relief" along normal blind 5.8
work_plane "WorkPlane64" AlongDistance 2.3 ExtraOffset 0
sketch "Guide nut crossed bridge relief" plane through (2.3, 0, 0) normal (1, 0, 0) x axis (0, 0, -1)
  line L1 (-40.4, -53.3) -> (-40.4, -56.7)
  line L2 (-40.6, -53.3) -> (-40.4, -53.3)
  line L3 (-40.6, -56.7) -> (-40.6, -53.3)
  line L4 (-40.4, -56.7) -> (-40.6, -56.7)
extrude "Extrude64" cut sketch "Guide nut crossed bridge relief" along normal blind 3.4
work_plane "WorkPlane1" AlongDistance 40.9 ExtraOffset 0
sketch "Guide nut envelope" plane through (0, 0, 40.9) normal (0, 0, 1) x axis (1, 0, 0)
  line L1 (4, -51.8246) -> (6.75, -53.4123)
  line L2 (1.25, -53.4123) -> (4, -51.8246)
  line L3 (1.25, -56.5877) -> (1.25, -53.4123)
  line L4 (4, -58.1754) -> (1.25, -56.5877)
  line L5 (6.75, -56.5877) -> (4, -58.1754)
  line L6 (6.75, -53.4123) -> (6.75, -56.5877)
extrude "Extrude1" new body sketch "Guide nut envelope" along normal blind 2.4
work_plane "WorkPlane2" AlongDistance 40.8 ExtraOffset 0
sketch "Guide nut thread" plane through (0, 0, 40.8) normal (0, 0, 1) x axis (1, 0, 0)
  circle C1 centre (4, -55) radius 1.5
extrude "Extrude2" cut sketch "Guide nut thread" along normal blind 2.6
work_plane "WorkPlane65" AlongDistance 40.8 ExtraOffset 0
sketch "Guide captive nut with lower reaction shoulder (1)" plane through (0, 0, 40.8) normal (0, 0, 1) x axis (1, 0, 0)
  line L1 (20, -51.6514) -> (22.9, -53.3257)
  line L2 (17.1, -53.3257) -> (20, -51.6514)
  line L3 (17.1, -56.6743) -> (17.1, -53.3257)
  line L4 (20, -58.3486) -> (17.1, -56.6743)
  line L5 (22.9, -56.6743) -> (20, -58.3486)
  line L6 (22.9, -53.3257) -> (22.9, -56.6743)
extrude "Extrude65" cut sketch "Guide captive nut with lower reaction shoulder (1)" along normal blind 2.6
work_plane "WorkPlane66" AlongDistance 17.1 ExtraOffset 0
sketch "Guide nut rear installation slot (1)" plane through (17.1, 0, 0) normal (1, 0, 0) x axis (0, 0, -1)
  line L1 (-40.8, -55) -> (-40.8, -74.1)
  line L2 (-43.4, -55) -> (-40.8, -55)
  line L3 (-43.4, -74.1) -> (-43.4, -55)
  line L4 (-40.8, -74.1) -> (-43.4, -74.1)
extrude "Extrude66" cut sketch "Guide nut rear installation slot (1)" along normal blind 5.8
work_plane "WorkPlane67" AlongDistance 17.1 ExtraOffset 0
sketch "Guide nut first bridge relief (1)" plane through (17.1, 0, 0) normal (1, 0, 0) x axis (0, 0, -1)
  line L1 (-40.6, -53.3) -> (-40.6, -56.7)
  line L2 (-40.8, -53.3) -> (-40.6, -53.3)
  line L3 (-40.8, -56.7) -> (-40.8, -53.3)
  line L4 (-40.6, -56.7) -> (-40.8, -56.7)
extrude "Extrude67" cut sketch "Guide nut first bridge relief (1)" along normal blind 5.8
work_plane "WorkPlane68" AlongDistance 18.3 ExtraOffset 0
sketch "Guide nut crossed bridge relief (1)" plane through (18.3, 0, 0) normal (1, 0, 0) x axis (0, 0, -1)
  line L1 (-40.4, -53.3) -> (-40.4, -56.7)
  line L2 (-40.6, -53.3) -> (-40.4, -53.3)
  line L3 (-40.6, -56.7) -> (-40.6, -53.3)
  line L4 (-40.4, -56.7) -> (-40.6, -56.7)
extrude "Extrude68" cut sketch "Guide nut crossed bridge relief (1)" along normal blind 3.4
work_plane "WorkPlane1" AlongDistance 40.9 ExtraOffset 0
sketch "Guide nut envelope" plane through (0, 0, 40.9) normal (0, 0, 1) x axis (1, 0, 0)
  line L1 (20, -51.8246) -> (22.75, -53.4123)
  line L2 (17.25, -53.4123) -> (20, -51.8246)
  line L3 (17.25, -56.5877) -> (17.25, -53.4123)
  line L4 (20, -58.1754) -> (17.25, -56.5877)
  line L5 (22.75, -56.5877) -> (20, -58.1754)
  line L6 (22.75, -53.4123) -> (22.75, -56.5877)
extrude "Extrude1" new body sketch "Guide nut envelope" along normal blind 2.4
work_plane "WorkPlane2" AlongDistance 40.8 ExtraOffset 0
sketch "Guide nut thread" plane through (0, 0, 40.8) normal (0, 0, 1) x axis (1, 0, 0)
  circle C1 centre (20, -55) radius 1.5
extrude "Extrude2" cut sketch "Guide nut thread" along normal blind 2.6
work_plane "WorkPlane69" AlongDistance -24 ExtraOffset 0
sketch "Close mounting insert pilot" plane through (-24, 0, 0) normal (1, 0, 0) x axis (0, 0, -1)
  circle C1 centre (-53.5, -62) radius 2.01
extrude "Extrude69" add sketch "Close mounting insert pilot" along normal blind 8.7
work_plane "WorkPlane70" AlongDistance -24.1 ExtraOffset 0
sketch "Block mount screw passage" plane through (-24.1, 0, 0) normal (1, 0, 0) x axis (0, 0, -1)
  circle C1 centre (-53.5, -62) radius 1.7
extrude "Extrude70" cut sketch "Block mount screw passage" along normal blind 8.9
work_plane "WorkPlane71" AlongDistance -20 ExtraOffset 0
sketch "Crossblock captive hex nut" plane through (-20, 0, 0) normal (1, 0, 0) x axis (0, 0, -1)
  line L1 (-56.4, -60.3257) -> (-53.5, -58.6514)
  line L2 (-56.4, -63.6743) -> (-56.4, -60.3257)
  line L3 (-53.5, -65.3486) -> (-56.4, -63.6743)
  line L4 (-50.6, -63.6743) -> (-53.5, -65.3486)
  line L5 (-50.6, -60.3257) -> (-50.6, -63.6743)
  line L6 (-53.5, -58.6514) -> (-50.6, -60.3257)
extrude "Extrude71" cut sketch "Crossblock captive hex nut" along normal blind 2.6
work_plane "WorkPlane72" AlongDistance -20 ExtraOffset 0
sketch "Top installation slot for block nut" plane through (-20, 0, 0) normal (1, 0, 0) x axis (0, 0, -1)
  line L1 (-53.5, -58.65) -> (-53.5, -65.35)
  line L2 (-59.1, -58.65) -> (-53.5, -58.65)
  line L3 (-59.1, -65.35) -> (-59.1, -58.65)
  line L4 (-53.5, -65.35) -> (-59.1, -65.35)
extrude "Extrude72" cut sketch "Top installation slot for block nut" along normal blind 2.6
work_plane "WorkPlane1" AlongDistance -19.9 ExtraOffset 0
sketch "Crossblock captive M3 (-62, -1)" plane through (-19.9, 0, 0) normal (1, 0, 0) x axis (0, 0, -1)
  line L1 (-56.25, -60.4123) -> (-53.5, -58.8246)
  line L2 (-56.25, -63.5877) -> (-56.25, -60.4123)
  line L3 (-53.5, -65.1754) -> (-56.25, -63.5877)
  line L4 (-50.75, -63.5877) -> (-53.5, -65.1754)
  line L5 (-50.75, -60.4123) -> (-50.75, -63.5877)
  line L6 (-53.5, -58.8246) -> (-50.75, -60.4123)
extrude "Extrude1" new body sketch "Crossblock captive M3 (-62, -1)" along normal blind 2.4 bodies "HARDWARE Crossblock captive M3 (-62, -1)"
work_plane "WorkPlane2" AlongDistance -20 ExtraOffset 0
sketch "Thread envelope" plane through (-20, 0, 0) normal (1, 0, 0) x axis (0, 0, -1)
  circle C1 centre (-53.5, -62) radius 1.5
extrude "Extrude2" cut sketch "Thread envelope" along normal blind 2.6
work_plane "WorkPlane73" AlongDistance 15.3 ExtraOffset 0
sketch "Close mounting insert pilot (1)" plane through (15.3, 0, 0) normal (1, 0, 0) x axis (0, 0, -1)
  circle C1 centre (-53.5, -62) radius 2.01
extrude "Extrude73" add sketch "Close mounting insert pilot (1)" along normal blind 8.7
work_plane "WorkPlane74" AlongDistance 15.2 ExtraOffset 0
sketch "Block mount screw passage (1)" plane through (15.2, 0, 0) normal (1, 0, 0) x axis (0, 0, -1)
  circle C1 centre (-53.5, -62) radius 1.7
extrude "Extrude74" cut sketch "Block mount screw passage (1)" along normal blind 8.9
work_plane "WorkPlane75" AlongDistance 17.4 ExtraOffset 0
sketch "Crossblock captive hex nut (1)" plane through (17.4, 0, 0) normal (1, 0, 0) x axis (0, 0, -1)
  line L1 (-56.4, -60.3257) -> (-53.5, -58.6514)
  line L2 (-56.4, -63.6743) -> (-56.4, -60.3257)
  line L3 (-53.5, -65.3486) -> (-56.4, -63.6743)
  line L4 (-50.6, -63.6743) -> (-53.5, -65.3486)
  line L5 (-50.6, -60.3257) -> (-50.6, -63.6743)
  line L6 (-53.5, -58.6514) -> (-50.6, -60.3257)
extrude "Extrude75" cut sketch "Crossblock captive hex nut (1)" along normal blind 2.6
work_plane "WorkPlane76" AlongDistance 17.4 ExtraOffset 0
sketch "Top installation slot for block nut (1)" plane through (17.4, 0, 0) normal (1, 0, 0) x axis (0, 0, -1)
  line L1 (-53.5, -58.65) -> (-53.5, -65.35)
  line L2 (-59.1, -58.65) -> (-53.5, -58.65)
  line L3 (-59.1, -65.35) -> (-59.1, -58.65)
  line L4 (-53.5, -65.35) -> (-59.1, -65.35)
extrude "Extrude76" cut sketch "Top installation slot for block nut (1)" along normal blind 2.6
work_plane "WorkPlane1" AlongDistance 17.5 ExtraOffset 0
sketch "Crossblock captive M3 (-62, 1)" plane through (17.5, 0, 0) normal (1, 0, 0) x axis (0, 0, -1)
  line L1 (-56.25, -60.4123) -> (-53.5, -58.8246)
  line L2 (-56.25, -63.5877) -> (-56.25, -60.4123)
  line L3 (-53.5, -65.1754) -> (-56.25, -63.5877)
  line L4 (-50.75, -63.5877) -> (-53.5, -65.1754)
  line L5 (-50.75, -60.4123) -> (-50.75, -63.5877)
  line L6 (-53.5, -58.8246) -> (-50.75, -60.4123)
extrude "Extrude1" new body sketch "Crossblock captive M3 (-62, 1)" along normal blind 2.4 bodies "HARDWARE Crossblock captive M3 (-62, 1)"
work_plane "WorkPlane2" AlongDistance 17.4 ExtraOffset 0
sketch "Thread envelope" plane through (17.4, 0, 0) normal (1, 0, 0) x axis (0, 0, -1)
  circle C1 centre (-53.5, -62) radius 1.5
extrude "Extrude2" cut sketch "Thread envelope" along normal blind 2.6
work_plane "WorkPlane77" AlongDistance -24 ExtraOffset 0
sketch "Close mounting insert pilot (2)" plane through (-24, 0, 0) normal (1, 0, 0) x axis (0, 0, -1)
  circle C1 centre (-53.5, -70) radius 2.01
extrude "Extrude77" add sketch "Close mounting insert pilot (2)" along normal blind 8.7
work_plane "WorkPlane78" AlongDistance -24.1 ExtraOffset 0
sketch "Block mount screw passage (2)" plane through (-24.1, 0, 0) normal (1, 0, 0) x axis (0, 0, -1)
  circle C1 centre (-53.5, -70) radius 1.7
extrude "Extrude78" cut sketch "Block mount screw passage (2)" along normal blind 8.9
work_plane "WorkPlane79" AlongDistance -20 ExtraOffset 0
sketch "Crossblock captive hex nut (2)" plane through (-20, 0, 0) normal (1, 0, 0) x axis (0, 0, -1)
  line L1 (-56.4, -68.3257) -> (-53.5, -66.6514)
  line L2 (-56.4, -71.6743) -> (-56.4, -68.3257)
  line L3 (-53.5, -73.3486) -> (-56.4, -71.6743)
  line L4 (-50.6, -71.6743) -> (-53.5, -73.3486)
  line L5 (-50.6, -68.3257) -> (-50.6, -71.6743)
  line L6 (-53.5, -66.6514) -> (-50.6, -68.3257)
extrude "Extrude79" cut sketch "Crossblock captive hex nut (2)" along normal blind 2.6
work_plane "WorkPlane80" AlongDistance -20 ExtraOffset 0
